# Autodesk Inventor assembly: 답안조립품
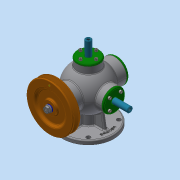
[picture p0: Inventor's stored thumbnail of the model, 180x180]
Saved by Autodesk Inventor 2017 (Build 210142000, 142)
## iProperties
Part Number: 답안조립품
Material: 일반
Document SubType Name: Assembly
Designer: MRC
Author: MRC
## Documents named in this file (17)
- C:\Users\MRC\Desktop\600911V1006\답안조립품.iam
- C:\Users\MRC\Desktop\600911V1006\본체.ipt
- C:\Users\MRC\Desktop\600911V1006\V-벨트풀리.ipt
- C:\Users\MRC\Desktop\600911V1006\너트 M8x1.ipt
- C:\Users\MRC\Desktop\600911V1006\뒤커버.ipt
- C:\Users\MRC\Desktop\600911V1006\베어링 6202.ipt
- C:\Users\MRC\Desktop\600911V1006\본체커버.ipt
- C:\Users\MRC\Desktop\600911V1006\볼트 M4.ipt
- C:\Users\MRC\Desktop\600911V1006\스프링1.ipt
- C:\Users\MRC\Desktop\600911V1006\스프링2.ipt
- C:\Users\MRC\Desktop\600911V1006\슬라이드 커버.ipt
- C:\Users\MRC\Desktop\600911V1006\슬라이드.ipt
- C:\Users\MRC\Desktop\600911V1006\앞커버.ipt
- C:\Users\MRC\Desktop\600911V1006\오일 실.ipt
- C:\Users\MRC\Desktop\600911V1006\와셔 8x17.ipt
- C:\Users\MRC\Desktop\600911V1006\축.ipt
- C:\Users\MRC\Desktop\600911V1006\키 4x4.ipt
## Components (1 placed, 1 different names)
1. V-벨트풀리:1
